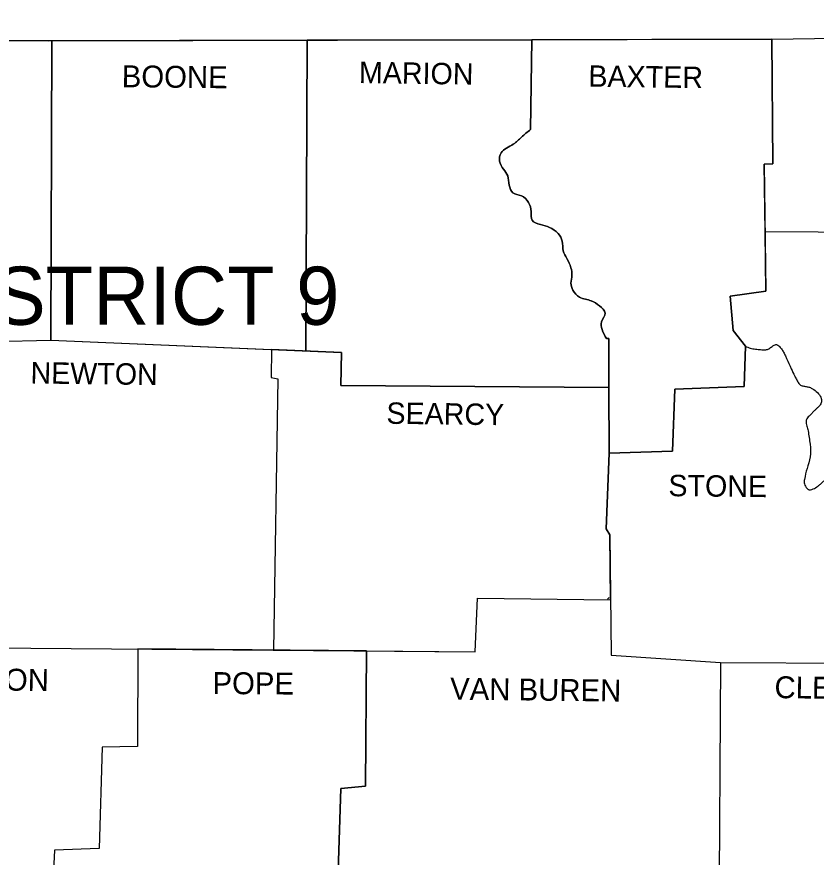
# Model space of a CAD drawing. Extents: x -13171 to 18763, y -8840 to 11152.
# Drawn here: x 12267 to 13801, y 8746 to 10358 of the extents above; entities that cross this region are included whole.
import ezdxf

# ---------------------------------------------------------------- set-up
doc = ezdxf.new("R2010")
doc.units = 0
for name, color, linetype in [('Level 1', 7, 'Continuous'), ('Level 2', 7, 'Continuous'), ('Level 3', 7, 'Continuous'), ('Level 48', 7, 'Continuous')]:
    doc.layers.add(name, color=color, linetype=linetype)

msp = doc.modelspace()

# ---------------------------------------------------------------- linework, layer by layer
at = {"layer": 'Level 1'}
for points in [[(10745.390580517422, 10312.988270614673), (12327.474404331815, 10312.009863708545), (13715.833678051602, 10314.94508427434), (15353.686690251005, 10340.383661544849), (16112.930380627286, 10357.994984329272)], [(14544.511469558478, 10327.815826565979), (14546.501066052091, 10081.105854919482), (14419.308179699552, 10074.257007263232), (14415.394552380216, 9941.193680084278), (13702.72503230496, 9945.136526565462)], [(11641.810298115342, 10007.87796022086), (11887.191336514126, 9999.898089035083), (11893.061777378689, 9968.589070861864), (11926.327609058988, 9967.610664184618), (11925.349202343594, 9948.042527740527), (11948.830965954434, 9942.172086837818), (11950.787779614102, 9835.52574368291), (11981.118390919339, 9828.676896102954), (11983.07520454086, 9786.60540295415), (12026.125104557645, 9780.73496205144), (12028.081918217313, 9741.598689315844), (12113.203311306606, 9732.793027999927), (12332.366438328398, 9737.685061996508), (12334.364140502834, 10312.024429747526)], [(12824.559789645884, 10313.060784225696), (12821.549825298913, 9717.087866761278)], [(13255.06133372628, 10313.970935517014), (13253.047253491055, 10141.767077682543)], [(13715.784347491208, 10314.944979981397), (13717.79049171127, 10076.2138209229), (13701.15757587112, 10075.235414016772), (13704.092796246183, 9831.612116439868), (13635.604319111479, 9821.828048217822), (13641.474760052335, 9756.274791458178), (13664.956523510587, 9725.944180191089), (13662.99970985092, 9648.650041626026), (13529.936382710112, 9643.758007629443), (13525.044348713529, 9524.392375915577), (13403.72190337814, 9520.478748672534), (13397.851462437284, 9375.67453968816), (13404.70031013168, 9363.933657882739), (13407.635530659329, 9133.029648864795), (13617.014589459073, 9119.331953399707), (13614.079369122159, 8603.711560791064), (13780.408528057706, 8598.819526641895), (13780.408528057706, 8074.393472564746), (13649.302014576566, 8064.6094043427), (13639.517946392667, 7949.157399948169), (13419.37641246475, 7948.178993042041)], [(13403.72190337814, 9520.478748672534), (13402.743496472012, 9740.620282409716)], [(12332.366438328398, 9737.685061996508), (12890.058324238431, 9714.203298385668), (12889.079917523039, 9650.606855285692), (13403.161030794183, 9646.675068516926)], [(12756.068637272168, 9719.844969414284), (12755.038183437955, 9666.26136441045), (12767.757471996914, 9663.326143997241), (12759.873931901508, 9143.01249916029)], [(12060.369343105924, 9148.684157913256), (13146.400910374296, 9139.878496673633), (13151.292944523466, 9242.611212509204), (13406.280234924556, 9239.64624397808)], [(13400.786682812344, 9240.65439892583), (13403.72190337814, 9243.589619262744)], [(12499.696812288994, 9145.12204334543), (12498.69559730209, 8957.894828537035), (12431.185526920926, 8956.91642185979), (12425.31508598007, 8762.213465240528), (12339.215285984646, 8759.278244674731), (12329.114520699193, 8551.202475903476)], [(12938.043358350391, 9141.567882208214), (12936.043444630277, 8881.5790968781), (12889.079917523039, 8877.665469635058), (12870.490187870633, 8302.362261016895)], [(13617.014589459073, 9119.331953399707), (14119.915693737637, 9116.396732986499), (14162.96559352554, 9136.943276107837), (14160.030373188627, 8754.386210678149), (14130.67816863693, 8741.666921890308), (14104.261184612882, 8719.163565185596), (14095.455523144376, 8710.35790371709), (14094.477116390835, 8600.776340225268), (13780.408528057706, 8598.819526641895)]]:
    msp.add_lwpolyline(points, dxfattribs=at)
for points in [[(13253.047253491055, 10141.767077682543), (13235.43593074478, 10127.090975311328), (13219.78142165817, 10113.39327984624), (13196.299658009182, 10096.760363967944), (13193.364437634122, 10081.105854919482), (13201.1916921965, 10065.451345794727), (13209.018946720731, 10052.732057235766), (13211.954167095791, 10035.120734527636), (13218.80301490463, 10020.444632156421), (13235.43593074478, 10014.57419125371), (13249.133626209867, 10001.854902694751), (13254.025660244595, 9984.243579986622), (13255.982473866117, 9967.610664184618), (13271.636982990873, 9959.783409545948), (13289.248305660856, 9953.91296871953), (13305.881221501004, 9942.172086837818), (13313.708476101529, 9927.495984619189), (13315.665289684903, 9908.906255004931), (13322.514137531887, 9894.230152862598), (13330.34139205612, 9876.618830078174), (13332.298205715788, 9861.942727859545), (13330.34139205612, 9847.26662548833), (13334.255019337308, 9833.568930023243), (13346.974307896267, 9819.871234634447), (13369.477664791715, 9813.022386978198), (13385.132173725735, 9803.238318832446), (13395.89464885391, 9789.540623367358), (13389.045801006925, 9772.907707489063), (13390.024207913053, 9758.231605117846), (13398.829869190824, 9740.620282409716)], [(13664.956523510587, 9725.944180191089), (13674.536631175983, 9722.267866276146), (13684.392192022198, 9720.332732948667), (13694.313986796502, 9719.491111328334), (13704.092796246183, 9719.095332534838), (13710.203004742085, 9721.14217366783), (13716.260185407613, 9725.532760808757), (13722.104112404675, 9728.9060491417), (13724.896035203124, 9729.160879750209), (13727.574559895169, 9727.900993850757), (13733.132547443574, 9722.282029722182), (13737.443129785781, 9716.026212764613), (13740.977656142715, 9709.348142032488), (13744.207475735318, 9702.462416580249), (13753.013137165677, 9682.894280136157), (13759.806412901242, 9668.473445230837), (13763.52149624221, 9661.413049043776), (13765.537518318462, 9657.942608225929), (13767.689239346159, 9654.520482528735), (13772.3110137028, 9650.784783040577), (13778.47398892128, 9649.156717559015), (13785.115030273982, 9648.009119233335), (13788.28259614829, 9647.107005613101), (13791.171003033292, 9645.714821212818), (13808.782325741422, 9630.060312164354), (13811.29452143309, 9621.60410125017), (13810.688811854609, 9617.175502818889), (13808.782325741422, 9613.427396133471), (13805.092685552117, 9609.37599466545), (13801.061828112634, 9605.584148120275), (13796.97759220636, 9601.800298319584), (13793.127816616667, 9597.77288708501), (13791.40996041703, 9595.925159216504), (13785.80674087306, 9590.426661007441), (13782.794857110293, 9586.508621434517), (13781.835485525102, 9584.387005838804), (13781.386934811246, 9582.118378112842), (13781.684448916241, 9577.524768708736), (13782.810367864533, 9572.885954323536), (13784.20297710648, 9568.215919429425), (13785.300562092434, 9563.528648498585), (13787.37107479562, 9550.819998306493), (13789.214189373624, 9538.090071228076), (13789.214189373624, 9513.629900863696), (13783.343748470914, 9491.12654408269), (13778.451714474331, 9470.580000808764), (13777.97909225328, 9466.1337535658), (13778.59340596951, 9461.700809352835), (13780.359882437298, 9457.304630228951), (13781.695565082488, 9455.127659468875), (13783.343748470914, 9452.968678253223), (13785.350799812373, 9451.286172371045), (13787.599956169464, 9450.545373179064), (13792.52132523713, 9451.176572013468), (13801.933477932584, 9455.903898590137), (13806.827693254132, 9459.369862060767), (13811.47379101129, 9463.647937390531), (13816.241766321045, 9467.723018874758), (13821.501614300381, 9470.580000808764), (13826.479893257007, 9471.8352341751), (13831.760779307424, 9472.32325636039), (13842.048157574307, 9470.580000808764), (13852.098929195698, 9465.71076804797), (13861.61629375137, 9459.817525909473), (13866.832349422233, 9454.900159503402), (13871.485167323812, 9448.96451781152), (13876.34018426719, 9443.807947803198), (13879.082716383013, 9442.083485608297), (13880.574598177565, 9441.53300262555), (13882.162837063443, 9441.227796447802), (13892.404272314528, 9442.186017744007), (13902.709380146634, 9445.141423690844), (13919.342296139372, 9450.033457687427), (13942.82405963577, 9456.882305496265), (13959.456975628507, 9448.076644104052), (13974.133077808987, 9436.33576222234), (13978.637900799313, 9431.787522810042), (13982.878859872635, 9426.989276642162), (13987.149758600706, 9422.216840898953), (13991.744400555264, 9417.74603276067), (14008.377316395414, 9406.005150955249), (14029.902266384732, 9395.242675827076), (14036.341631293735, 9393.123663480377), (14042.995096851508, 9391.679141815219), (14049.706393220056, 9390.304175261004), (14056.319250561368, 9388.393828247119), (14070.15410519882, 9382.408022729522), (14076.116220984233, 9377.949027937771), (14078.641218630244, 9375.106347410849), (14079.762548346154, 9373.500878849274), (14080.779420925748, 9371.760912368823), (14082.38735002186, 9368.249023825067), (14084.720885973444, 9357.645765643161), (14084.916912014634, 9350.530441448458), (14084.693048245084, 9343.38711453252), (14083.714641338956, 9318.926944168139), (14081.757827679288, 9288.59633290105), (14079.80101401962, 9255.330501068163), (14079.405650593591, 9247.225351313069), (14079.44836545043, 9239.11723940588), (14080.401209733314, 9231.043902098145), (14081.366446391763, 9227.03206665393), (14082.736234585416, 9223.043076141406), (14087.910407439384, 9211.999318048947), (14093.498709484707, 9201.518126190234), (14100.440632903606, 9188.969256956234), (14107.196404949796, 9176.079548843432), (14110.295095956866, 9164.523093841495), (14110.810457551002, 9158.560531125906), (14111.110032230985, 9152.597785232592), (14111.59161208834, 9134.510449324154), (14110.288276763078, 9116.452924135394)]]:
    msp.add_spline(points, degree=3, dxfattribs=at)
at = {"layer": 'Level 48'}
for p, q in [((12334.364140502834, 10312.024429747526), (12332.366438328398, 9737.685061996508)), ((12332.366438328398, 9737.685061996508), (12334.364140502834, 10312.024429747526)), ((12824.559789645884, 10313.060784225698), (12334.364140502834, 10312.024429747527)), ((12821.549825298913, 9717.087866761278), (12824.559789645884, 10313.060784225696)), ((12821.549825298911, 9717.087866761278), (12824.559789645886, 10313.060784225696)), ((12824.559789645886, 10313.060784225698), (12821.549825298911, 9717.087866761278)), ((12824.559789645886, 10313.060784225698), (12821.549825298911, 9717.087866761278)), ((12824.559789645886, 10313.060784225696), (12821.549825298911, 9717.087866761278)), ((13255.061333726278, 10313.970935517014), (12824.559789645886, 10313.060784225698)), ((13255.061333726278, 10313.970935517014), (12824.559789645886, 10313.060784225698)), ((13255.061333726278, 10313.970935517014), (12824.559789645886, 10313.060784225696)), ((13255.06133372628, 10313.970935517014), (13253.047253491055, 10141.767077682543)), ((13253.047253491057, 10141.767077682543), (13255.061333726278, 10313.970935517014)), ((13253.047253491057, 10141.767077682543), (13255.061333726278, 10313.970935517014)), ((13715.833678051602, 10314.94508427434), (13255.06133372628, 10313.970935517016)), ((13398.829869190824, 9740.620282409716), (13402.743496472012, 9740.620282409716)), ((13398.829869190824, 9740.620282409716), (13402.743496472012, 9740.620282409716)), ((13402.743496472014, 9740.620282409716), (13398.829869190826, 9740.620282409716)), ((13402.743496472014, 9740.620282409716), (13398.829869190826, 9740.620282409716)), ((13403.161030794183, 9646.675068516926), (13402.743496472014, 9740.620282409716)), ((12332.366438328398, 9737.685061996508), (12756.068637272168, 9719.844969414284)), ((12756.068637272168, 9719.844969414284), (12821.549825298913, 9717.087866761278)), ((13403.72190337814, 9520.478748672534), (13403.161030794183, 9646.675068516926)), ((12938.043358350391, 9141.567882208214), (12499.696812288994, 9145.12204334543)), ((12759.873931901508, 9143.01249916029), (12938.043358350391, 9141.567882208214))]:
    msp.add_line(p, q, dxfattribs=at)
for points in [[(12334.364140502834, 10312.024429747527), (12327.474404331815, 10312.009863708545), (11648.578114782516, 10312.429713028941)], [(12824.559789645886, 10313.060784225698), (13255.061333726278, 10313.970935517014)], [(13403.72190337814, 9520.478748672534), (13525.044348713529, 9524.392375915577), (13529.936382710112, 9643.758007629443), (13662.99970985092, 9648.650041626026), (13664.956523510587, 9725.944180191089), (13641.474760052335, 9756.274791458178), (13635.604319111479, 9821.828048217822), (13704.092796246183, 9831.612116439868), (13702.72503230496, 9945.136526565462), (13701.15757587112, 10075.235414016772), (13717.79049171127, 10076.2138209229), (13715.833678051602, 10314.94508427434)], [(11641.810298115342, 10007.87796022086), (11887.191336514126, 9999.898089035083), (11893.061777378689, 9968.589070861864), (11926.327609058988, 9967.610664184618), (11925.349202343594, 9948.042527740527), (11948.830965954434, 9942.172086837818), (11950.787779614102, 9835.52574368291), (11981.118390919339, 9828.676896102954), (11983.07520454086, 9786.60540295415), (12026.125104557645, 9780.73496205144), (12028.081918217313, 9741.598689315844), (12111.08531866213, 9733.012130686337), (12113.203311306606, 9732.793027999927), (12332.366438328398, 9737.685061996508)], [(13402.743496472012, 9740.620282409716), (13403.161030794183, 9646.675068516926), (13403.72190337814, 9520.478748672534)], [(13403.161030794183, 9646.675068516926), (13402.743496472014, 9740.620282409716)], [(12756.068637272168, 9719.844969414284), (12755.038183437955, 9666.26136441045), (12767.757471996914, 9663.326143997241), (12759.873931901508, 9143.01249916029)], [(13403.161030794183, 9646.675068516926), (12889.079917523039, 9650.606855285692), (12890.058324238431, 9714.203298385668), (12756.068637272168, 9719.844969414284)], [(12821.549825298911, 9717.08786676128), (12890.058324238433, 9714.203298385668), (12889.07991752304, 9650.606855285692), (13403.161030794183, 9646.675068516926)], [(12821.549825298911, 9717.087866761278), (12890.058324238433, 9714.203298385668), (12889.07991752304, 9650.606855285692), (13403.161030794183, 9646.675068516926)], [(13406.280234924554, 9239.64624397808), (13404.70031013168, 9363.933657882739), (13397.851462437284, 9375.67453968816), (13403.72190337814, 9520.478748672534)], [(12938.043358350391, 9141.567882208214), (13146.400910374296, 9139.878496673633), (13151.292944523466, 9242.611212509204), (13406.280234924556, 9239.64624397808)], [(12499.696812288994, 9145.12204334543), (12498.69559730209, 8957.894828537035), (12431.185526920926, 8956.91642185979), (12425.31508598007, 8762.213465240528), (12339.215285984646, 8759.278244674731), (12329.114520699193, 8551.202475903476)], [(12870.490187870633, 8302.362261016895), (12889.079917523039, 8877.665469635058), (12936.043444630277, 8881.5790968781), (12938.043358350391, 9141.567882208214)]]:
    msp.add_lwpolyline(points, dxfattribs=at)
for points in [[(13253.047253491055, 10141.767077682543), (13235.43593074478, 10127.090975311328), (13219.78142165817, 10113.39327984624), (13196.299658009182, 10096.760363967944), (13193.364437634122, 10081.105854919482), (13201.1916921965, 10065.451345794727), (13209.018946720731, 10052.732057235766), (13211.954167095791, 10035.120734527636), (13218.80301490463, 10020.444632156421), (13235.43593074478, 10014.57419125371), (13249.133626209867, 10001.854902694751), (13254.025660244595, 9984.243579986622), (13255.982473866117, 9967.610664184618), (13271.636982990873, 9959.783409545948), (13289.248305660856, 9953.91296871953), (13305.881221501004, 9942.172086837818), (13313.708476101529, 9927.495984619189), (13315.665289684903, 9908.906255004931), (13322.514137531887, 9894.230152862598), (13330.34139205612, 9876.618830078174), (13332.298205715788, 9861.942727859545), (13330.34139205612, 9847.26662548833), (13334.255019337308, 9833.568930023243), (13346.974307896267, 9819.871234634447), (13369.477664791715, 9813.022386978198), (13385.132173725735, 9803.238318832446), (13395.89464885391, 9789.540623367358), (13389.045801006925, 9772.907707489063), (13390.024207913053, 9758.231605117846), (13398.829869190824, 9740.620282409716)], [(13398.829869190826, 9740.620282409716), (13390.024207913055, 9758.231605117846), (13389.045801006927, 9772.907707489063), (13395.894648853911, 9789.540623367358), (13385.132173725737, 9803.238318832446), (13369.477664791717, 9813.022386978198), (13346.97430789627, 9819.871234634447), (13334.25501933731, 9833.568930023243), (13330.341392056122, 9847.26662548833), (13332.29820571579, 9861.942727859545), (13330.341392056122, 9876.618830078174), (13322.514137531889, 9894.230152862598), (13315.665289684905, 9908.906255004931), (13313.70847610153, 9927.495984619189), (13305.881221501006, 9942.172086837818), (13289.248305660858, 9953.91296871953), (13271.636982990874, 9959.783409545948), (13255.98247386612, 9967.610664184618), (13254.025660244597, 9984.243579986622), (13249.133626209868, 10001.854902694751), (13235.435930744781, 10014.57419125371), (13218.803014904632, 10020.444632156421), (13211.954167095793, 10035.120734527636), (13209.018946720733, 10052.732057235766), (13201.191692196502, 10065.451345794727), (13193.364437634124, 10081.105854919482), (13196.299658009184, 10096.760363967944), (13219.781421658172, 10113.39327984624), (13235.435930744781, 10127.090975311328), (13253.047253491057, 10141.767077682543)], [(13398.829869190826, 9740.620282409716), (13390.024207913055, 9758.231605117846), (13389.045801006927, 9772.907707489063), (13395.894648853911, 9789.540623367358), (13385.132173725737, 9803.238318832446), (13369.477664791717, 9813.022386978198), (13346.97430789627, 9819.871234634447), (13334.25501933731, 9833.568930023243), (13330.341392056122, 9847.26662548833), (13332.29820571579, 9861.942727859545), (13330.341392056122, 9876.618830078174), (13322.514137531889, 9894.230152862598), (13315.665289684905, 9908.906255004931), (13313.70847610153, 9927.495984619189), (13305.881221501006, 9942.172086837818), (13289.248305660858, 9953.91296871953), (13271.636982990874, 9959.783409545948), (13255.98247386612, 9967.610664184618), (13254.025660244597, 9984.243579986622), (13249.133626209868, 10001.854902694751), (13235.435930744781, 10014.57419125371), (13218.803014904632, 10020.444632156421), (13211.954167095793, 10035.120734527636), (13209.018946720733, 10052.732057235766), (13201.191692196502, 10065.451345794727), (13193.364437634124, 10081.105854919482), (13196.299658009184, 10096.760363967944), (13219.781421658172, 10113.39327984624), (13235.435930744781, 10127.090975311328), (13253.047253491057, 10141.767077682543)]]:
    msp.add_spline(points, degree=3, dxfattribs=at)

# ---------------------------------------------------------------- texts
at = {"layer": 'Level 2'}
for s, height, rotation, p in [('MARION', 41.09308632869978, 359.18542221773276, (12923.324156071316, 10230.80209790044)), ('BOONE', 42.0734499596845, 359.40006668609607, (12468.364986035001, 10222.974843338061)), ('BAXTER', 41.09308632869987, 359.25594171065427, (13363.607223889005, 10223.953250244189)), ('NEWTON', 41.09308632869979, 359.2717028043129, (12293.2301655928, 9654.520482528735)), ('SEARCY', 41.081345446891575, 359.2527055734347, (12976.158124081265, 9577.226343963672)), ('STONE', 41.08134544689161, 359.40006668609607, (13517.217094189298, 9438.292575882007)), ('JOHNSON', 42.073449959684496, 359.35139723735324, (12053.52049548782, 9067.47639210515)), ('POPE', 42.073449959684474, 359.61546944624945, (12642.521399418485, 9058.670730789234)), ('VAN BUREN', 42.07344995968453, 359.3507833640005, (13098.458976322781, 9047.908255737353)), ('CLEBURNE', 42.06170907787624, 359.2535166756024, (13720.72571223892, 9050.84347630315))]:
    msp.add_text(s, height=height, rotation=rotation, dxfattribs=at).set_placement(p)
at = {"layer": 'Level 3'}
msp.add_text('DISTRICT 9', height=111.53837717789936, dxfattribs=at).set_placement((12074.067038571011, 9767.037266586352))

doc.saveas('drawing.dxf')
